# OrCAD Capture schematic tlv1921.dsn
size A
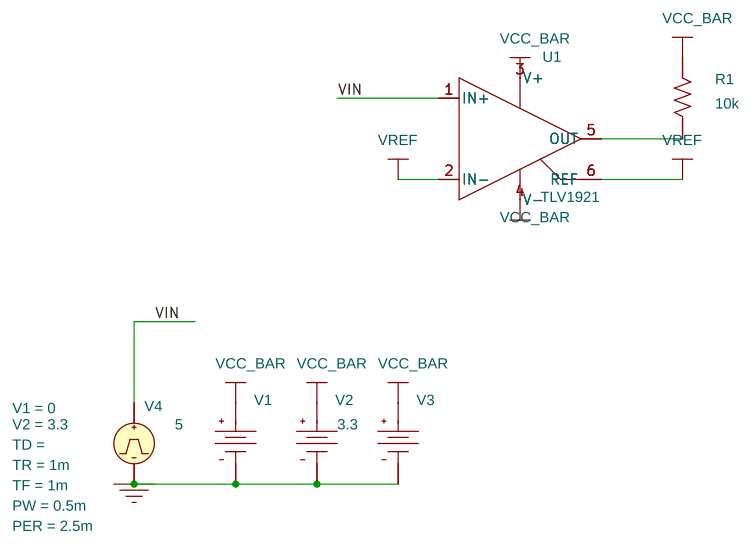
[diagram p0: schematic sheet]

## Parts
R1  10k  [AXRC05]
U1  TLV1921
V1  VDC
V2  VDC
V3  VDC
V4  VPULSE

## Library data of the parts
R1 = R
U1 = TLV1921
V1 = VDC: DC: 5
V2 = VDC
V3 = VDC: DC: 3.3
V4 = VPULSE: PER: 2.5m; PW: 0.5m; TF: 1m; TR: 1m; V1: 0; V2: 3.3

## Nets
VCC: U1.3(V+) V1.0(+)
VEE: U1.4(V-) V2.0(+)
VIN: U1.1(IN+) V4.1(+)
0: V1.1(-) V2.1(-) V3.1(-) V4.2(-)
VPU: R1.2 V3.0(+)
VREF: U1.2(IN-) U1.6(REF)
N00208: R1.1 U1.5(OUT)
